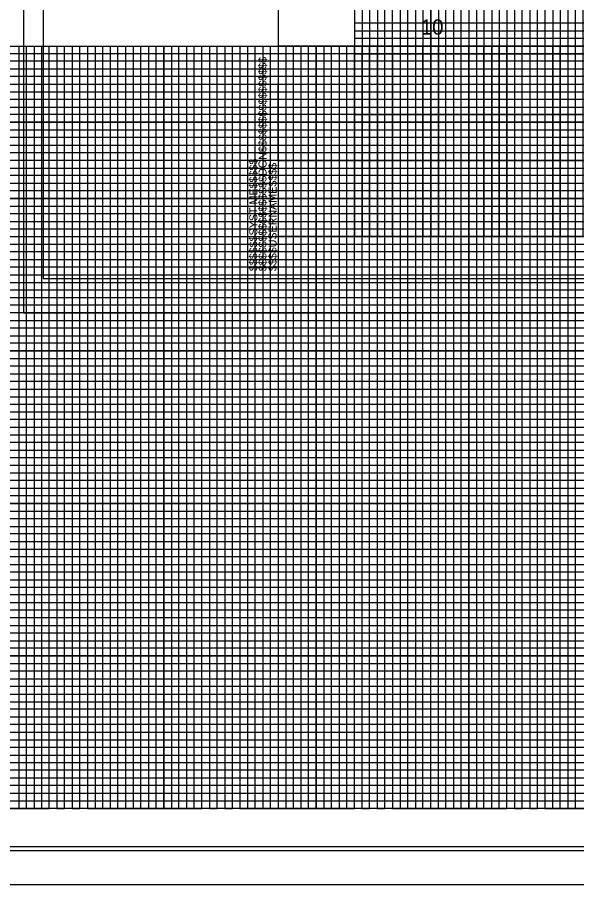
# Model space of a CAD drawing. Extents: x 553912 to 567693, y 512355 to 537539.
# Drawn here: x 566005 to 566372, y 513390 to 513959 of the extents above; entities that cross this region are included whole.
import ezdxf

# ---------------------------------------------------------------- set-up
doc = ezdxf.new("R2010")
doc.units = 0
for name, color, linetype in [('Default', 7, 'Continuous'), ('Exist Vertical Profile Horizontal Axis Label Major', 7, 'Continuous'), ('Old_Level_42', 7, 'Continuous'), ('Old_Level_51', 7, 'Continuous'), ('Old_Level_53', 7, 'Continuous'), ('Old_Level_54', 7, 'Continuous'), ('Prop ROW Permanent Easement CELL', 7, 'Continuous'), ('Sheet Cutting Line CELL', 7, 'Continuous'), ('Sheet DOT Grid CELL', 7, 'Continuous'), ('Sheet Layout Profile Border Port 2', 7, 'Continuous'), ('Sheet Plot Border Inside CELL', 7, 'Continuous'), ('Sheet Plot Border Outside CELL', 7, 'Continuous'), ('Sheet Profile CELL', 7, 'Continuous'), ('Sheet Profile Grid Major CELL', 7, 'Continuous'), ('Sheet Profile Grid Middle CELL', 7, 'Continuous'), ('Sheet Profile Grid Minor CELL', 7, 'Continuous'), ('Sheet Row Area Data CELL', 7, 'Continuous'), ('Sheet Summary Guardrail CELL', 7, 'Continuous')]:
    doc.layers.add(name, color=color, linetype=linetype)

msp = doc.modelspace()

# ---------------------------------------------------------------- linework, layer by layer
at = {"layer": 'Default'}
msp.add_lwpolyline([(567693.42, 514864.71), (566009.42, 514864.71), (566009.42, 513764.71), (567693.42, 513764.71)], close=True, dxfattribs=at)
at = {"layer": 'Old_Level_42'}
for p, q in [((566226.42, 514839.71), (566226.42, 513814.71)), ((566276.42, 514839.71), (566276.42, 513814.71)), ((566326.42, 514839.71), (566326.42, 513814.71)), ((566176.42, 513914.71), (567676.42, 513914.71)), ((566176.42, 513864.71), (567676.42, 513864.71))]:
    msp.add_line(p, q, dxfattribs=at)
at = {"layer": 'Old_Level_51'}
msp.add_lwpolyline([(567688.92, 514842.26), (566022.42, 514842.26), (566022.42, 513787.16), (567688.92, 513787.16)], close=True, dxfattribs=at)
at = {"layer": 'Old_Level_53'}
for p, q in [((567676.42, 513814.71), (566176.42, 513814.71)), ((566176.42, 513789.71), (566176.42, 513789.71)), ((566176.42, 513789.71), (566176.42, 513789.71)), ((566176.42, 513789.71), (566176.42, 513789.71)), ((566176.42, 513789.71), (566176.42, 513789.71)), ((566176.42, 513789.71), (566176.42, 513789.71)), ((566176.42, 513789.71), (566176.42, 513789.71))]:
    msp.add_line(p, q, dxfattribs=at)
msp.add_lwpolyline([(567676.42, 514839.71), (566176.42, 514839.71), (566176.42, 513789.71), (567676.42, 513789.71)], close=True, dxfattribs=at)
msp.add_lwpolyline([(566213.92, 513789.71), (566213.92, 513789.71)], dxfattribs=at)
at = {"layer": 'Old_Level_54'}
for points in [[(566176.42, 514839.71), (566226.42, 514839.71), (566226.42, 513814.71), (566276.42, 513814.71), (566276.42, 514839.71), (566326.42, 514839.71), (566326.42, 513814.71), (566376.42, 513814.71), (566376.42, 514839.71), (566426.42, 514839.71), (566426.42, 513814.71), (566476.42, 513814.71), (566476.42, 514839.71), (566526.42, 514839.71), (566526.42, 513814.71), (566576.42, 513814.71), (566576.42, 514839.71), (566626.42, 514839.71), (566626.42, 513814.71), (566676.42, 513814.71), (566676.42, 514839.71), (566726.42, 514839.71), (566726.42, 513814.71), (566776.42, 513814.71)], [(567676.42, 513864.71), (566176.42, 513864.71), (566176.42, 513914.71), (567676.42, 513914.71)]]:
    msp.add_lwpolyline(points, dxfattribs=at)
at = {"layer": 'Prop ROW Permanent Easement CELL'}
for points in [[(566251.42, 513814.71), (566251.42, 514839.71), (566301.42, 514839.71), (566301.42, 513814.71), (566351.42, 513814.71), (566351.42, 514839.71), (566401.42, 514839.71), (566401.42, 513814.71), (566451.42, 513814.71), (566451.42, 514839.71), (566501.42, 514839.71), (566501.42, 513814.71), (566551.42, 513814.71), (566551.42, 514839.71), (566601.42, 514839.71), (566601.42, 513814.71), (566651.42, 513814.71), (566651.42, 514839.71), (566701.42, 514839.71), (566701.42, 513814.71), (566751.42, 513814.71), (566751.42, 514839.71), (566801.42, 514839.71)], [(567676.42, 513939.71), (566176.42, 513939.71), (566176.42, 513889.71), (567676.42, 513889.71)], [(567676.42, 513839.71), (566176.42, 513839.71)]]:
    msp.add_lwpolyline(points, dxfattribs=at)
at = {"layer": 'Sheet Cutting Line CELL'}
msp.add_line((565534.35, 513389.72), (567218.35, 513389.72), dxfattribs=at)
at = {"layer": 'Sheet DOT Grid CELL'}
for p, q in [((565701.35, 513939.72), (567201.24, 513939.72)), ((566051.35, 513939.72), (566051.35, 513439.72)), ((566101.35, 513939.72), (566101.35, 513439.72)), ((566151.35, 513939.72), (566151.35, 513439.72)), ((566201.35, 513939.72), (566201.35, 513439.72)), ((566251.35, 513939.72), (566251.35, 513439.72)), ((566301.35, 513939.72), (566301.35, 513439.72)), ((566351.35, 513939.72), (566351.35, 513439.72)), ((565701.35, 513889.72), (567201.24, 513889.72)), ((565701.35, 513839.72), (567201.24, 513839.72)), ((565701.35, 513789.72), (567201.24, 513789.72)), ((565701.35, 513739.72), (567201.24, 513739.72)), ((565701.35, 513689.72), (567201.24, 513689.72)), ((565701.35, 513639.72), (567201.24, 513639.72)), ((565701.35, 513589.72), (567201.24, 513589.72)), ((565701.35, 513539.72), (567201.24, 513539.72)), ((565701.35, 513489.72), (567201.24, 513489.72))]:
    msp.add_line(p, q, dxfattribs=at)
at = {"layer": 'Sheet Layout Profile Border Port 2'}
msp.add_lwpolyline([(565751.35, 513939.72), (567151.35, 513939.72), (567151.35, 513439.72), (565751.35, 513439.72)], close=True, dxfattribs=at)
at = {"layer": 'Sheet Plot Border Inside CELL'}
msp.add_lwpolyline([(565547.35, 513412.17), (567213.85, 513412.17), (567213.85, 514467.27), (565547.35, 514467.27)], close=True, dxfattribs=at)
at = {"layer": 'Sheet Plot Border Outside CELL'}
msp.add_lwpolyline([(565534.35, 513389.72), (567218.35, 513389.72), (567218.35, 514489.72), (565534.35, 514489.72)], close=True, dxfattribs=at)
at = {"layer": 'Sheet Profile CELL'}
for p, q in [((565701.35, 513939.72), (567201.35, 513939.72)), ((567201.35, 513439.72), (565701.35, 513439.72)), ((565701.35, 513414.72), (567201.35, 513414.72))]:
    msp.add_line(p, q, dxfattribs=at)
msp.add_lwpolyline([(567201.35, 514464.72), (565701.35, 514464.72), (565701.35, 513414.72), (567201.35, 513414.72)], close=True, dxfattribs=at)
at = {"layer": 'Sheet Profile Grid Major CELL'}
for p, q in [((566201.35, 513939.72), (566251.35, 513939.72)), ((566301.35, 513939.72), (566351.35, 513939.72))]:
    msp.add_line(p, q, dxfattribs=at)
for points in [[(566001.35, 513939.72), (566051.35, 513939.72), (566051.35, 513439.72), (566101.35, 513439.72), (566101.35, 513939.72), (566151.35, 513939.72), (566151.35, 513439.72), (566201.35, 513439.72), (566201.35, 513939.72), (566251.35, 513939.72), (566251.35, 513439.72), (566301.35, 513439.72), (566301.35, 513939.72), (566351.35, 513939.72), (566351.35, 513439.72), (566401.35, 513439.72)], [(567201.35, 513889.72), (565701.35, 513889.72)], [(567201.35, 513839.72), (565701.35, 513839.72), (565701.35, 513789.72), (567201.35, 513789.72)], [(567201.35, 513739.72), (565701.35, 513739.72), (565701.35, 513689.72), (567201.35, 513689.72)], [(567201.35, 513639.72), (565701.35, 513639.72), (565701.35, 513589.72), (567201.35, 513589.72)], [(567201.35, 513539.72), (565701.35, 513539.72), (565701.35, 513539.72), (565701.35, 513489.72), (567201.35, 513489.72)], [(567201.35, 513439.72), (565701.35, 513439.72)]]:
    msp.add_lwpolyline(points, dxfattribs=at)
at = {"layer": 'Sheet Profile Grid Middle CELL'}
for points in [[(565976.35, 513439.72), (566026.35, 513439.72), (566026.35, 513939.72), (566076.35, 513939.72), (566076.35, 513439.72), (566126.35, 513439.72), (566126.35, 513939.72), (566176.35, 513939.72), (566176.35, 513439.72), (566226.35, 513439.72), (566226.35, 513939.72), (566276.35, 513939.72), (566276.35, 513439.72), (566326.35, 513439.72), (566326.35, 513439.72), (566326.35, 513939.72), (566376.35, 513939.72)], [(565701.35, 513914.72), (567201.35, 513914.72)], [(567201.35, 513864.72), (565701.35, 513864.72), (565701.35, 513814.72), (567201.35, 513814.72)], [(567201.35, 513764.72), (565701.35, 513764.72), (565701.35, 513714.72), (567201.35, 513714.72)], [(567201.35, 513664.72), (565701.35, 513664.72), (565701.35, 513614.72), (567201.35, 513614.72)], [(567201.35, 513564.72), (565701.35, 513564.72), (565701.35, 513514.72), (567201.35, 513514.72)], [(567201.35, 513464.72), (565701.35, 513464.72)]]:
    msp.add_lwpolyline(points, dxfattribs=at)
at = {"layer": 'Sheet Profile Grid Minor CELL'}
for p, q in [((565751.35, 513934.72), (567151.35, 513934.72)), ((567151.35, 513929.72), (565751.35, 513929.72)), ((565751.35, 513924.72), (567151.35, 513924.72)), ((567151.35, 513919.72), (565751.35, 513919.72)), ((565751.35, 513909.72), (567151.35, 513909.72)), ((567151.35, 513904.72), (565751.35, 513904.72)), ((565751.35, 513899.72), (567151.35, 513899.72)), ((567151.35, 513894.72), (565751.35, 513894.72)), ((565751.35, 513884.72), (567151.35, 513884.72)), ((567151.35, 513879.72), (565751.35, 513879.72)), ((565751.35, 513874.72), (567151.35, 513874.72)), ((567151.35, 513869.72), (565751.35, 513869.72)), ((565751.35, 513859.72), (567151.35, 513859.72)), ((567151.35, 513854.72), (565751.35, 513854.72)), ((565751.35, 513849.72), (567151.35, 513849.72)), ((567151.35, 513844.72), (565751.35, 513844.72)), ((565751.35, 513834.72), (567151.35, 513834.72)), ((567151.35, 513829.72), (565751.35, 513829.72)), ((565751.35, 513824.72), (567151.35, 513824.72)), ((567151.35, 513819.72), (565751.35, 513819.72)), ((565751.35, 513809.72), (567151.35, 513809.72)), ((567151.35, 513804.72), (565751.35, 513804.72)), ((565751.35, 513799.72), (567151.35, 513799.72)), ((567151.35, 513794.72), (565751.35, 513794.72)), ((565751.35, 513784.72), (567151.35, 513784.72)), ((567151.35, 513779.72), (565751.35, 513779.72)), ((565751.35, 513774.72), (567151.35, 513774.72)), ((567151.35, 513769.72), (565751.35, 513769.72)), ((565751.35, 513759.72), (567151.35, 513759.72)), ((567151.35, 513754.72), (565751.35, 513754.72)), ((565751.35, 513749.72), (567151.35, 513749.72)), ((567151.35, 513744.72), (565751.35, 513744.87)), ((565751.35, 513734.72), (567151.35, 513734.72)), ((567151.35, 513729.72), (565751.35, 513729.72)), ((565751.35, 513724.72), (567151.35, 513724.72)), ((567151.35, 513719.72), (565751.35, 513719.72)), ((565751.35, 513709.72), (567151.35, 513709.72)), ((567151.35, 513704.72), (565751.35, 513704.72)), ((565751.35, 513699.72), (567151.35, 513699.72)), ((567151.35, 513694.72), (565751.35, 513694.72)), ((565751.35, 513684.72), (567151.35, 513684.72)), ((567151.35, 513679.72), (565751.35, 513679.72)), ((565751.35, 513674.72), (567151.35, 513674.72)), ((567151.35, 513669.72), (565751.35, 513669.72)), ((565751.35, 513659.72), (567151.35, 513659.72)), ((567151.35, 513654.72), (565751.35, 513654.72)), ((565751.35, 513649.72), (567151.35, 513649.72)), ((567151.35, 513644.72), (565751.35, 513644.72)), ((565751.35, 513634.72), (567151.35, 513634.72)), ((567151.35, 513629.72), (565751.35, 513629.72)), ((565751.35, 513624.72), (567151.35, 513624.72)), ((567151.35, 513619.72), (565751.35, 513619.72)), ((565751.35, 513609.72), (567151.35, 513609.72)), ((567151.35, 513604.72), (565751.35, 513604.72)), ((565751.35, 513599.72), (567151.35, 513599.72)), ((567151.35, 513594.72), (565751.35, 513594.72)), ((565751.35, 513584.72), (567151.35, 513584.72)), ((567151.35, 513579.72), (565751.35, 513579.72)), ((565751.35, 513574.72), (567151.35, 513574.72)), ((567151.35, 513569.72), (565751.35, 513569.72)), ((565751.35, 513559.72), (567151.35, 513559.72)), ((567151.35, 513554.72), (565751.35, 513554.72)), ((565751.35, 513549.72), (567151.35, 513549.72)), ((567151.35, 513544.72), (565751.35, 513544.72)), ((565751.35, 513534.72), (567151.35, 513534.72)), ((567151.35, 513529.72), (565751.35, 513529.72)), ((565751.35, 513524.72), (567151.35, 513524.72)), ((567151.35, 513519.72), (565751.35, 513519.72)), ((565751.35, 513509.72), (567151.35, 513509.72)), ((567151.35, 513504.72), (565751.35, 513504.72)), ((565751.35, 513499.72), (567151.35, 513499.72)), ((567151.35, 513494.72), (565751.35, 513494.72)), ((565751.35, 513484.72), (567151.35, 513484.72)), ((567151.35, 513479.72), (565751.35, 513479.72)), ((565751.35, 513474.72), (567151.35, 513474.72)), ((567151.35, 513469.72), (565751.35, 513469.72)), ((565751.35, 513459.72), (567151.35, 513459.72)), ((567151.35, 513454.72), (565751.35, 513454.72)), ((565751.35, 513449.72), (567151.35, 513449.72)), ((565751.35, 513444.72), (567151.35, 513444.72))]:
    msp.add_line(p, q, dxfattribs=at)
for points in [[(565996.35, 513939.72), (566006.35, 513939.72), (566006.35, 513439.72), (566011.35, 513439.72), (566011.35, 513939.72), (566016.35, 513939.72), (566016.35, 513439.72), (566021.35, 513439.72), (566021.35, 513939.72), (566031.35, 513939.72), (566031.35, 513439.72), (566036.35, 513439.72), (566036.35, 513939.72), (566041.35, 513939.72), (566041.35, 513439.72), (566046.35, 513439.72), (566046.35, 513939.72), (566056.35, 513939.72), (566056.35, 513439.72), (566061.35, 513439.72), (566061.35, 513939.72), (566066.35, 513939.72), (566066.35, 513439.72), (566071.35, 513439.72), (566071.35, 513939.72), (566081.35, 513939.72), (566081.35, 513439.72), (566086.35, 513439.72), (566086.35, 513939.72), (566091.35, 513939.72), (566091.35, 513439.72), (566096.35, 513439.72), (566096.35, 513939.72), (566106.35, 513939.72), (566106.35, 513439.72), (566111.35, 513439.72), (566111.35, 513939.72), (566116.35, 513939.72), (566116.35, 513439.72), (566121.35, 513439.72), (566121.35, 513939.72), (566131.35, 513939.72), (566131.35, 513439.72), (566136.35, 513439.72), (566136.35, 513939.72), (566141.35, 513939.72), (566141.35, 513439.72), (566146.35, 513439.72), (566146.35, 513939.72), (566156.35, 513939.72), (566156.35, 513439.72), (566161.35, 513439.72), (566161.35, 513939.72), (566166.35, 513939.72), (566166.35, 513439.72), (566171.35, 513439.72), (566171.35, 513939.72), (566181.35, 513939.72), (566181.35, 513439.72), (566186.35, 513439.72), (566186.35, 513939.72), (566191.35, 513939.72), (566191.35, 513439.72), (566196.35, 513439.72), (566196.35, 513939.72), (566206.35, 513939.72), (566206.35, 513439.72), (566211.35, 513439.72), (566211.35, 513939.72), (566216.35, 513939.72), (566216.35, 513439.72), (566221.35, 513439.72), (566221.35, 513939.72), (566231.35, 513939.72), (566231.35, 513439.72), (566236.35, 513439.72), (566236.35, 513939.72), (566241.35, 513939.72), (566241.35, 513439.72), (566246.35, 513439.72), (566246.35, 513939.72), (566256.35, 513939.72), (566256.35, 513439.72), (566261.35, 513439.72), (566261.35, 513939.72), (566266.35, 513939.72), (566266.35, 513439.72), (566271.35, 513439.72), (566271.35, 513939.72), (566281.35, 513939.72)], [(566281.35, 513939.72), (566281.35, 513439.72), (566286.35, 513439.72), (566286.35, 513939.72), (566291.35, 513939.72), (566291.35, 513439.72), (566296.35, 513439.72), (566296.35, 513939.72), (566306.35, 513939.72), (566306.35, 513439.72), (566311.35, 513439.72), (566311.35, 513939.72), (566316.35, 513939.72), (566316.35, 513439.72), (566321.35, 513439.72), (566321.35, 513939.72), (566331.35, 513939.72), (566331.35, 513439.72), (566336.35, 513439.72), (566336.35, 513939.72), (566341.35, 513939.72), (566341.35, 513439.72), (566346.35, 513439.72), (566346.35, 513939.72), (566356.35, 513939.72), (566356.35, 513439.72), (566361.35, 513439.72), (566361.35, 513939.72), (566366.35, 513939.72), (566366.35, 513439.72), (566371.35, 513439.72), (566371.35, 513939.72), (566381.35, 513939.72)]]:
    msp.add_lwpolyline(points, dxfattribs=at)
at = {"layer": 'Sheet Row Area Data CELL'}
for p, q in [((566009.42, 514864.71), (566009.42, 513764.71)), ((566009.42, 513764.71), (567693.42, 513764.71))]:
    msp.add_line(p, q, dxfattribs=at)
at = {"layer": 'Sheet Summary Guardrail CELL'}
for points in [[(566231.42, 514839.71), (566231.42, 513814.71), (566236.42, 513814.71), (566236.42, 514839.71)], [(566241.42, 514839.71), (566241.42, 513814.71), (566246.42, 513814.71), (566246.42, 514839.71)], [(566256.42, 514839.71), (566256.42, 513814.71), (566261.42, 513814.71), (566261.42, 514839.71)], [(566266.42, 514839.71), (566266.42, 513814.71), (566271.42, 513814.71), (566271.42, 514839.71)], [(566281.42, 514839.71), (566281.42, 513814.71), (566286.42, 513814.71), (566286.42, 514839.71)], [(566291.42, 514839.71), (566291.42, 513814.71), (566296.42, 513814.71), (566296.42, 514839.71)], [(566306.42, 514839.71), (566306.42, 513814.71), (566311.42, 513814.71), (566311.42, 514839.71)], [(566316.42, 514839.71), (566316.42, 513814.71), (566321.42, 513814.71), (566321.42, 514839.71)], [(566331.42, 514839.71), (566331.42, 513814.71), (566336.42, 513814.71), (566336.42, 514839.71)], [(566341.42, 514839.71), (566341.42, 513814.71), (566346.42, 513814.71), (566346.42, 514839.71)], [(566356.42, 514839.71), (566356.42, 513814.71), (566361.42, 513814.71), (566361.42, 514839.71)], [(566366.42, 514839.71), (566366.42, 513814.71), (566371.42, 513814.71), (566371.42, 514839.71)], [(567626.42, 513954.71), (566226.42, 513954.71), (566226.42, 513949.71), (567626.42, 513949.71)], [(567626.42, 513944.71), (566226.42, 513944.71), (566226.42, 513934.71), (567626.42, 513934.71)], [(567626.42, 513929.71), (566226.42, 513929.71), (566226.42, 513924.71), (567626.42, 513924.71)], [(567626.42, 513919.71), (566226.42, 513919.71), (566226.42, 513909.71), (567626.42, 513909.71)], [(567626.42, 513904.71), (566226.42, 513904.71), (566226.42, 513899.71), (567626.42, 513899.71)], [(567626.42, 513894.71), (566226.42, 513894.71), (566226.42, 513884.71), (567626.42, 513884.71)], [(567626.42, 513879.71), (566226.42, 513879.71), (566226.42, 513874.71), (567626.42, 513874.71)], [(567626.42, 513869.71), (566226.42, 513869.71), (566226.42, 513859.71), (567626.42, 513859.71)], [(567626.42, 513854.71), (566226.42, 513854.71), (566226.42, 513849.71), (567626.42, 513849.71)], [(567626.42, 513844.71), (566226.42, 513844.71), (566226.42, 513834.71), (567626.42, 513834.71)], [(567626.42, 513829.71), (566226.42, 513829.71), (566226.42, 513824.71), (567626.42, 513824.71)], [(567626.42, 513819.71), (566226.42, 513819.71)]]:
    msp.add_lwpolyline(points, dxfattribs=at)

# ---------------------------------------------------------------- texts
at = {"layer": 'Exist Vertical Profile Horizontal Axis Label Major'}
msp.add_text('10', height=10, dxfattribs=at).set_placement((566269.94, 513947.22))
at = {"layer": 'Old_Level_53'}
for s, p in [('$$$$$$$$$$$$$$$$DGN$$$$$$$$$$$$$$$$', (566168.77, 513792.07)), ('$$$$$$SYSTIME$$$$$', (566162.72, 513792.07)), ('$$$$USERNAME$$$$', (566175.34, 513792.09))]:
    msp.add_text(s, height=5.25, rotation=90, dxfattribs=at).set_placement(p)

doc.saveas('drawing.dxf')
